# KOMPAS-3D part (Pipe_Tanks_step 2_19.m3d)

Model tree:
1. X Axis
2. Y Axis
3. Z Axis  (labels: Pipe Dn 50; Valve Dy 50)
     Òîëùèíà ñòåíêè 1 = 1

Referenced files in C:\Documents and Settings\kashirsky\Мои документы\Camtasia Studio\Pipelines3D\Tanks\: Tanks_step 2.a3d
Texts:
  Pipe Dn 50
  Steel ASTM A295
  Three Point Plane
  Plane at Angle
  Line and Point Plane
  Axis through Two Vertices
  Axis of Feature
  Axis of Conical Surface
  Axis through Edge
  Trim by Surface
  Trim by Sketch
  Feature with No History
  Intersection Axis of Two Planes
  Two Line Plane
  Line and Face Plane
  Bend by line
  Hole in sheet body
  Cut in sheet body
  Point in CM
  Linear Dimension from Line to Point
  Surface Finish Symbol
  Geometric Tolerance Symbol
  Leader #1
  Leader #2
  Leader #3
  Shape Deviations and Datum
  Node point number
  Mark of coordination axis
  Node point designation
  Mark/Reference designation with leader
  Mark/reference designation on line
  Mark/Reference designation without leader
  Valve Dy 50
  Plane of section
